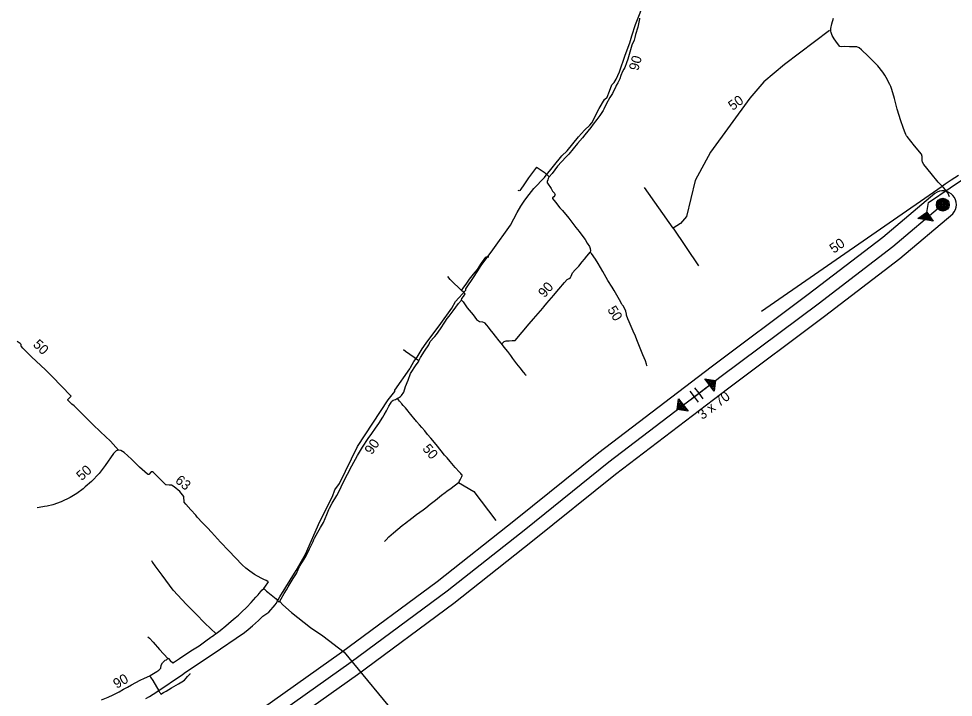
# Model space of a CAD drawing. Extents: x -444817 to -434929, y -1145681 to -1129851.
# Drawn here: x -442712 to -441954, y -1130962 to -1130412 of the extents above; entities that cross this region are included whole.
import ezdxf

# ---------------------------------------------------------------- set-up
doc = ezdxf.new("R2010")
doc.units = 0
for name, color, linetype in [('Vrstva 10', 7, 'Continuous'), ('Vrstva 11', 7, 'Continuous'), ('Vrstva 13', 7, 'Continuous'), ('Vrstva 15', 7, 'Continuous'), ('Vrstva 18', 7, 'Continuous'), ('Vrstva 27', 7, 'Continuous'), ('Vrstva 30', 7, 'Continuous'), ('Vrstva 35', 7, 'Continuous'), ('Vrstva 38', 7, 'Continuous'), ('Vrstva 58', 7, 'Continuous')]:
    doc.layers.add(name, color=color, linetype=linetype)

msp = doc.modelspace()

# ---------------------------------------------------------------- linework, layer by layer
at = {"layer": 'Vrstva 10'}
for p, q in [((-442167.4, -1130713.98), (-442164.01, -1130718.43)), ((-442163.61, -1130711.1), (-442160.22, -1130715.55)), ((-442160.22, -1130715.55), (-442156.83, -1130720.01)), ((-442164.01, -1130718.43), (-442160.62, -1130722.89))]:
    msp.add_line(p, q, dxfattribs=at)
for points in [[(-442543.87, -1131005.45), (-442442.17, -1130933.34), (-442364.32, -1130875.82), (-442300.6, -1130825.49), (-442233.21, -1130771.17), (-442142.12, -1130701.84), (-442063.4, -1130643.16), (-442002.57, -1130596.62), (-441962.3, -1130562.43)], [(-442172.7, -1130725.05), (-442162.12, -1130716.99), (-442151.53, -1130708.94)]]:
    msp.add_lwpolyline(points, dxfattribs=at)
for points in [[(-442155.35, -1130703.92), (-442146.52, -1130705.12), (-442147.72, -1130713.95)], [(-442153.77, -1130704.85), (-442147.31, -1130705.72), (-442148.18, -1130712.18)], [(-442152.19, -1130705.77), (-442148.09, -1130706.32), (-442148.65, -1130710.41)], [(-442150.61, -1130706.69), (-442148.88, -1130706.92), (-442149.12, -1130708.64)], [(-442176.52, -1130720.03), (-442168.88, -1130730.06), (-442177.71, -1130728.86)], [(-442176.05, -1130721.8), (-442170.46, -1130729.14), (-442176.93, -1130728.26)], [(-442175.58, -1130723.57), (-442172.05, -1130728.22), (-442176.14, -1130727.66)], [(-442175.12, -1130725.34), (-442173.63, -1130727.3), (-442175.35, -1130727.06)]]:
    msp.add_lwpolyline(points, close=True, dxfattribs=at)
at = {"layer": 'Vrstva 11'}
for radius in [5.25, 4.55, 3.85, 3.15, 2.45, 1.75, 1.05, 0.35]:
    msp.add_circle((-441962.15, -1130562.69), radius, dxfattribs=at)
at = {"layer": 'Vrstva 15'}
for points in [[(-441968.62, -1130553.5), (-442010.81, -1130589.32), (-442071.36, -1130635.64), (-442150.07, -1130694.32), (-442241.33, -1130763.77), (-442308.79, -1130818.15), (-442372.32, -1130868.34), (-442449.95, -1130925.69), (-442551.7, -1130997.84)], [(-442511.53, -1130996.32), (-442437.05, -1130943.51), (-442358.97, -1130885.82), (-442295.07, -1130835.35), (-442227.76, -1130781.09), (-442136.83, -1130711.89), (-442058.1, -1130653.2), (-441997, -1130606.45), (-441954.08, -1130570.1)]]:
    msp.add_lwpolyline(points, dxfattribs=at)
msp.add_arc((-441962.27, -1130562.6), 11.1, 317.50257, 124.90759, dxfattribs=at)
at = {"layer": 'Vrstva 18'}
msp.add_lwpolyline([(-441975.84, -1130573.79), (-441973.68, -1130560.84), (-441938.52, -1130537.09), (-441896.26, -1130510.56), (-441885.41, -1130506.39), (-441864.4, -1130498), (-441823.77, -1130476.32), (-441821.75, -1130474.03), (-441814.82, -1130469.54), (-441767.01, -1130447.94), (-441721.98, -1130422.65), (-441673.35, -1130395.2), (-441719.61, -1130299.27), (-441714.03, -1130296.36)], dxfattribs=at)
for points in [[(-441969.98, -1130576.19), (-441982.36, -1130573.88), (-441975.01, -1130568.84)], [(-441971.51, -1130575.19), (-441980.57, -1130573.5), (-441975.2, -1130569.82)], [(-441973.04, -1130574.2), (-441978.78, -1130573.12), (-441975.38, -1130570.79)], [(-441974.58, -1130573.2), (-441976.99, -1130572.75), (-441975.56, -1130571.76)]]:
    msp.add_lwpolyline(points, close=True, dxfattribs=at)
at = {"layer": 'Vrstva 27'}
for points in [[(-442208.2, -1130411.49), (-442208.3, -1130411.94), (-442209.73, -1130418.71), (-442211.51, -1130424.6), (-442212.15, -1130427.18), (-442212.65, -1130429.19), (-442214.45, -1130433.28), (-442216.13, -1130439.14), (-442217.86, -1130444.64), (-442218.73, -1130447.74), (-442220.3, -1130451.38), (-442221.02, -1130452.76), (-442222.1, -1130454.69), (-442223.41, -1130457.92), (-442224.26, -1130460.77), (-442225.8, -1130463.81), (-442227.12, -1130465.98), (-442227.4, -1130466.84), (-442227.85, -1130467.76), (-442228.85, -1130469.66), (-442230.13, -1130472.5), (-442232.42, -1130475.81), (-442235.19, -1130481.27), (-442237.14, -1130485.18), (-442237.76, -1130486.34), (-442240.52, -1130490.32), (-442242.89, -1130493.56), (-442245.96, -1130497.55), (-442247.87, -1130500)], [(-441994.27, -1130500), (-441996.11, -1130494.73), (-441999.09, -1130485.29), (-442001.43, -1130476.55), (-442003.49, -1130469.28), (-442004.29, -1130466.9), (-442005.11, -1130465.27), (-442008.04, -1130459.62), (-442009.22, -1130457.82), (-442010.94, -1130455.32), (-442014.99, -1130450.03), (-442022.65, -1130442.38), (-442028.22, -1130437.2), (-442030.04, -1130435.62), (-442031.87, -1130434.82), (-442035.46, -1130434.73), (-442037.75, -1130434.6), (-442042.06, -1130434.37), (-442043.97, -1130434.71), (-442045.64, -1130434.34), (-442046.75, -1130433.21), (-442049.07, -1130430.15), (-442050.26, -1130428.27), (-442051.88, -1130425.52), (-442052.67, -1130423.1), (-442052.98, -1130422.13), (-442053.1, -1130419.95), (-442052.32, -1130416.01), (-442050.91, -1130411.56)], [(-442247.87, -1130500), (-442250.29, -1130503.1), (-442252.71, -1130506.19), (-442254.54, -1130508.41), (-442258.54, -1130513.22), (-442265.66, -1130521.68), (-442268.09, -1130524.15), (-442274.83, -1130531.51), (-442279.22, -1130537.52), (-442281.59, -1130540.08)], [(-441949.36, -1130538.97), (-441955.35, -1130542.79), (-441960.27, -1130546.03), (-441962.44, -1130547.59), (-441962.74, -1130547.8), (-441965.95, -1130544.37), (-441971.72, -1130537.34), (-441977.54, -1130530.04), (-441978.58, -1130528.29), (-441978.93, -1130526.93), (-441978.82, -1130523.52), (-441979.49, -1130521.79), (-441985.14, -1130514.87), (-441991.07, -1130507.53), (-441991.6, -1130506.77), (-441992.03, -1130505.89), (-441993.24, -1130502.96), (-441994.27, -1130500)], [(-442291.86, -1130532.26), (-442293.5, -1130534.34), (-442298.37, -1130540.81), (-442302.22, -1130546.52), (-442304.59, -1130550.11), (-442305.44, -1130551.26), (-442306.03, -1130551.54), (-442306.68, -1130551.07)], [(-442281.59, -1130540.08), (-442284.89, -1130537.26), (-442291.32, -1130532.73), (-442291.86, -1130532.26)], [(-442281.59, -1130540.08), (-442281.92, -1130540.44), (-442282.37, -1130541.45), (-442282.77, -1130542.51), (-442283.29, -1130543.91), (-442283.21, -1130545.01), (-442282.95, -1130545.37), (-442280.01, -1130549.48), (-442278.78, -1130551.68), (-442277.22, -1130553.46), (-442276.85, -1130554.39), (-442276.61, -1130554.7), (-442276.87, -1130555.21), (-442277.89, -1130556.25), (-442278.86, -1130557.03), (-442278.95, -1130557.34), (-442278.8, -1130557.7), (-442276.4, -1130560.61), (-442272.79, -1130565.13), (-442270.84, -1130567.52), (-442265.7, -1130573.69), (-442259.83, -1130581.08), (-442257.28, -1130584.49), (-442254.94, -1130587.37), (-442252.29, -1130591.04), (-442250.71, -1130593.82), (-442248.82, -1130596.69), (-442248.31, -1130598.28), (-442248.06, -1130600.2), (-442248.38, -1130601.16)], [(-441956.63, -1130556.34), (-441958.03, -1130553.11), (-441959.86, -1130550.64), (-441961.52, -1130548.79), (-441962.74, -1130547.8)], [(-442320.61, -1130675.22), (-442319.77, -1130675.24), (-442318, -1130673.6), (-442316.5, -1130673.1), (-442314.08, -1130673.02), (-442311.65, -1130672.81), (-442309.84, -1130672.87), (-442309.29, -1130672.67), (-442303.37, -1130665.98), (-442297.79, -1130659.41), (-442294.18, -1130655.11), (-442292.52, -1130653.2), (-442290.57, -1130651.03), (-442286.77, -1130646.54), (-442285.98, -1130645.6), (-442283.39, -1130642.49), (-442279.7, -1130638.26), (-442277.87, -1130636.14), (-442276.71, -1130634.79), (-442273.61, -1130631.14), (-442269.14, -1130625.83), (-442266.9, -1130623.42), (-442265.42, -1130622.43), (-442264.32, -1130621.65), (-442263.64, -1130620.72), (-442263.12, -1130619.28), (-442262.65, -1130617.96), (-442260.54, -1130615.63), (-442257.6, -1130612.52), (-442254.77, -1130609.08), (-442253.03, -1130606.84), (-442251.01, -1130604.47), (-442249.25, -1130602.43), (-442248.38, -1130601.16)], [(-442201.94, -1130693.46), (-442202.21, -1130693.17), (-442202.65, -1130691.93), (-442203.45, -1130689.31), (-442205.53, -1130684.39), (-442208.76, -1130676.37), (-442210.5, -1130672.15), (-442211.65, -1130669.38), (-442213.38, -1130665.19), (-442216.65, -1130657.73), (-442217.63, -1130655.34), (-442218.73, -1130652.39), (-442218.94, -1130651.34), (-442219.32, -1130649.02), (-442219.85, -1130647.62), (-442221.48, -1130644.78), (-442222.29, -1130643.91), (-442222.7, -1130643.48), (-442224.43, -1130639.7), (-442227.65, -1130634.29), (-442228.93, -1130632.16), (-442230.36, -1130629.68), (-442233.87, -1130624.07), (-442238.08, -1130616.86), (-442241.92, -1130610.41), (-442244.07, -1130606.83), (-442247.26, -1130602.3), (-442248.38, -1130601.16)], [(-442352.69, -1130632.19), (-442350.93, -1130629.68), (-442349.03, -1130627.11), (-442346.18, -1130623.08), (-442343.03, -1130619.16), (-442339.76, -1130615.19), (-442336.51, -1130610), (-442332.91, -1130605.29), (-442332.52, -1130605.05), (-442331.52, -1130604.93), (-442330.64, -1130604.95)], [(-442353.75, -1130631.17), (-442360.16, -1130624.99), (-442361.82, -1130623.33), (-442363.89, -1130620.79)], [(-442352.69, -1130632.19), (-442353.49, -1130631.42), (-442353.75, -1130631.17)], [(-442352.75, -1130640.01), (-442352.32, -1130638.86), (-442351.13, -1130637.01), (-442349.75, -1130635.02), (-442351.18, -1130633.69), (-442352.69, -1130632.19)], [(-442387.32, -1130689.35), (-442386.01, -1130686.48), (-442382.71, -1130681.51), (-442379.25, -1130676.28), (-442378.01, -1130673.54), (-442374.87, -1130670.06), (-442374.38, -1130669.55), (-442373.1, -1130667.99), (-442369.84, -1130663.28), (-442366.23, -1130657.88), (-442364.28, -1130654.99), (-442362.81, -1130653.05), (-442359.56, -1130648.67), (-442355.25, -1130642.91), (-442352.75, -1130640.01)], [(-442352.75, -1130640.01), (-442351.33, -1130641.47), (-442348.04, -1130646.25), (-442343.34, -1130651.95), (-442340.59, -1130655.7), (-442338.07, -1130657.38), (-442335.73, -1130657.72), (-442334.28, -1130658.1), (-442334.08, -1130658.35), (-442332.49, -1130660.29), (-442331.1, -1130661.99), (-442329.7, -1130663.86), (-442327.39, -1130666.83), (-442325.44, -1130669.32), (-442322.51, -1130673.1), (-442320.92, -1130675), (-442320.61, -1130675.22)], [(-442631.13, -1130761.67), (-442633.22, -1130759.18), (-442637.66, -1130754.31), (-442645.64, -1130746.8), (-442652, -1130740.82), (-442660.31, -1130732.56), (-442666.92, -1130725.88), (-442669.04, -1130724.31), (-442672.06, -1130721.31), (-442672.23, -1130721.05), (-442672.06, -1130720.75), (-442669.36, -1130717.93), (-442677.57, -1130709.44), (-442684.69, -1130702.29), (-442690.38, -1130696.7), (-442694.05, -1130693.1), (-442701.54, -1130685.97), (-442708.79, -1130678.92), (-442709.62, -1130677.75), (-442709.92, -1130677.36), (-442710.08, -1130675.98), (-442710.88, -1130675.26), (-442713.18, -1130673.54)], [(-442320.61, -1130675.22), (-442318.48, -1130678.11), (-442315.37, -1130681.85), (-442313, -1130684.89), (-442311.23, -1130687.28), (-442307.97, -1130691.59), (-442305.32, -1130695.09), (-442302.73, -1130698.36), (-442300.88, -1130700.73), (-442300.45, -1130701.22)], [(-442387.32, -1130689.35), (-442391.21, -1130686.5), (-442398.2, -1130681.76), (-442399.9, -1130680.39)], [(-442404.65, -1130719.63), (-442403.79, -1130719.17), (-442402.14, -1130718.14), (-442401.31, -1130717.43), (-442399.57, -1130714.59), (-442398.21, -1130710.1), (-442396.1, -1130704.97), (-442393.96, -1130699.64), (-442389.62, -1130692.47), (-442387.62, -1130690), (-442387.32, -1130689.35)], [(-442500, -1130884.03), (-442498.94, -1130882.24), (-442496.5, -1130877.86), (-442494.71, -1130874.85), (-442493.35, -1130872.5), (-442490.9, -1130868.51), (-442489.18, -1130865.74), (-442486.72, -1130861.6), (-442485.2, -1130858.46), (-442484.18, -1130856.15), (-442481.71, -1130852.34), (-442478.99, -1130847.84), (-442476, -1130841.74), (-442473.1, -1130835.79), (-442472.63, -1130834.21), (-442472.03, -1130833.09), (-442469.21, -1130828.13), (-442467.07, -1130824.33), (-442464.75, -1130820.34), (-442463.33, -1130817.18), (-442462.07, -1130813.91), (-442460.31, -1130809.81), (-442459.82, -1130808.79), (-442457.54, -1130804.64), (-442453.9, -1130798.59), (-442452.25, -1130795.41), (-442450.47, -1130791.56), (-442448.47, -1130787.49), (-442445.3, -1130781.06), (-442441.74, -1130774.54), (-442437.18, -1130766.17), (-442433.17, -1130759.16), (-442428.46, -1130752.2), (-442425.55, -1130748.19), (-442422.5, -1130743.9), (-442419.83, -1130740.21), (-442416.57, -1130734.92), (-442415.44, -1130733.09), (-442413.68, -1130729.78), (-442411.64, -1130725.93), (-442410.44, -1130723.75), (-442409.89, -1130723.02), (-442409.41, -1130722.21), (-442408.03, -1130721.23), (-442406.28, -1130720.57), (-442404.65, -1130719.63)], [(-442404.31, -1130825.74), (-442400.75, -1130822.87), (-442397.82, -1130820.7), (-442396.27, -1130819.36), (-442395.56, -1130818.81), (-442393.06, -1130816.86), (-442389.17, -1130814), (-442383.92, -1130810.07), (-442381.75, -1130808.44), (-442378.08, -1130805.45), (-442373.92, -1130802.27), (-442368.88, -1130798.25), (-442366.08, -1130796.12), (-442364.62, -1130795.05), (-442361.02, -1130792.4), (-442355.27, -1130788), (-442354.61, -1130787.25), (-442354.21, -1130786.56), (-442353.84, -1130785.73), (-442352.52, -1130783.05), (-442352.21, -1130782.23), (-442352.21, -1130782.2), (-442352.24, -1130781.82), (-442352.58, -1130781.38), (-442353.17, -1130780.71), (-442354.3, -1130779.43), (-442357.73, -1130775.74), (-442361.93, -1130770.89), (-442364.33, -1130767.96), (-442366.37, -1130765.64), (-442369.22, -1130762.35), (-442373.4, -1130757.23), (-442377.55, -1130752.09), (-442380.25, -1130749.07), (-442382.55, -1130746.15), (-442385.01, -1130743.32), (-442386.82, -1130741.29), (-442389.11, -1130738.47), (-442389.68, -1130737.77), (-442390.26, -1130737.08), (-442393.73, -1130732.9), (-442395.13, -1130731.1), (-442395.89, -1130730.17), (-442398.27, -1130727.48), (-442400.03, -1130725.42), (-442401.01, -1130724.28), (-442401.65, -1130723.48), (-442401.97, -1130723.13), (-442402.91, -1130722.08), (-442404.6, -1130719.69), (-442404.65, -1130719.63)], [(-442631.13, -1130761.67), (-442631.29, -1130761.72), (-442633.01, -1130762.3), (-442634.97, -1130764.35), (-442641.8, -1130774.19), (-442646.64, -1130780.62), (-442653.07, -1130787.17), (-442657.97, -1130791.51), (-442659.65, -1130793), (-442664.92, -1130796.9), (-442670.3, -1130800.21), (-442677.67, -1130803.68), (-442684.33, -1130806.12), (-442688.95, -1130807.11), (-442691.11, -1130807.51), (-442695.3, -1130808.24), (-442697.13, -1130808.46)], [(-442602.71, -1130779.69), (-442603.48, -1130779.37), (-442604.45, -1130779.32), (-442606.52, -1130781.39), (-442606.86, -1130781.47), (-442607.46, -1130781.28), (-442613.91, -1130775.41), (-442620.53, -1130768.88), (-442626.35, -1130763.61), (-442629.05, -1130762.08), (-442630.9, -1130761.59), (-442631.13, -1130761.67)], [(-442592.28, -1130789.81), (-442592.7, -1130789.71), (-442592.71, -1130789.72), (-442602.71, -1130779.69)], [(-442577.85, -1130803.83), (-442578.01, -1130799.34), (-442581.21, -1130795.23), (-442585.74, -1130791.57), (-442587.9, -1130790.01), (-442589.92, -1130789.96), (-442592.28, -1130789.81)], [(-442567.09, -1130815.96), (-442568.42, -1130814.49), (-442572.38, -1130809.95), (-442576.42, -1130805.44), (-442576.32, -1130805.54), (-442577.85, -1130803.83)], [(-442513.19, -1130873.94), (-442511.81, -1130871.97), (-442509.75, -1130869.31), (-442509.34, -1130868.5), (-442509.73, -1130868.07), (-442511.08, -1130867.46), (-442513.19, -1130866.56), (-442515.32, -1130865.48), (-442520.57, -1130862.51), (-442524.45, -1130859.74), (-442526.55, -1130858.15), (-442527.59, -1130857.37), (-442530.6, -1130854.55), (-442536.15, -1130848.89), (-442541.4, -1130843.45), (-442548.16, -1130836.24), (-442555.55, -1130828.17), (-442558.88, -1130824.72), (-442562.93, -1130820.52), (-442567.09, -1130815.96)], [(-442415.28, -1130835.64), (-442413.95, -1130834.39), (-442411.65, -1130832.01), (-442407.94, -1130828.86), (-442404.31, -1130825.74)], [(-442551.99, -1130910.44), (-442556.22, -1130906.67), (-442561.34, -1130901.65), (-442568.01, -1130894.68), (-442575.79, -1130886.87), (-442586.71, -1130875.16), (-442595.64, -1130862.98), (-442601.36, -1130855.51), (-442603.29, -1130852.73), (-442603.65, -1130852.12), (-442603.92, -1130851.48)], [(-442551.99, -1130910.44), (-442551.72, -1130910.23), (-442548.56, -1130907.88), (-442543.89, -1130904.2), (-442539.48, -1130900.44), (-442536.29, -1130897.59), (-442533.59, -1130895.42), (-442531.1, -1130893.04), (-442527.03, -1130889), (-442523.49, -1130885.17), (-442519.55, -1130880.9), (-442517.68, -1130878.91), (-442516.78, -1130877.96), (-442515.51, -1130876.3), (-442514.6, -1130875.11), (-442513.19, -1130873.94)], [(-442513.19, -1130873.94), (-442511.02, -1130875.96), (-442509.81, -1130876.82), (-442503.12, -1130882.28), (-442502.01, -1130883.66), (-442500.69, -1130885.02), (-442500.2, -1130884.37), (-442500, -1130884.03)], [(-442607.15, -1130912.96), (-442605.99, -1130914.13), (-442602.79, -1130917.45), (-442597.68, -1130923.38), (-442591.13, -1130930.6)], [(-442591.13, -1130930.6), (-442590.74, -1130930.25), (-442589.08, -1130932.18), (-442587.04, -1130934.19), (-442585.49, -1130933.21), (-442581.56, -1130930.63), (-442577.28, -1130927.7), (-442571.11, -1130923.6), (-442565.71, -1130920.22), (-442560.1, -1130916.22), (-442555.98, -1130913.22), (-442555.34, -1130912.68), (-442553.86, -1130911.86), (-442551.99, -1130910.44)], [(-442605.65, -1130944.6), (-442605.32, -1130944.44), (-442602.56, -1130942.85), (-442600.05, -1130941.28), (-442598.34, -1130940.09), (-442597.51, -1130939.2), (-442596.67, -1130938.47), (-442596.32, -1130935.94), (-442595.34, -1130934.22), (-442594.72, -1130933.45), (-442593.07, -1130932.02), (-442592.19, -1130931.63), (-442591.32, -1130930.77), (-442591.13, -1130930.6)], [(-442596.62, -1130959.52), (-442594.54, -1130958.31), (-442592.25, -1130956.98), (-442587.94, -1130954.38), (-442582.46, -1130951.02), (-442579.71, -1130949.63), (-442577.61, -1130948.1), (-442576.05, -1130946.54), (-442574.94, -1130945.32), (-442573.08, -1130943.41), (-442572.79, -1130943.11), (-442572.81, -1130942.94), (-442572.84, -1130942.78)], [(-442644.93, -1130964.24), (-442639.49, -1130962.01), (-442635.36, -1130959.97), (-442630.59, -1130957.63), (-442626.89, -1130955.51), (-442623.7, -1130953.84), (-442620.43, -1130951.84), (-442613.54, -1130948.05), (-442609.85, -1130946.56), (-442605.65, -1130944.6)], [(-442605.65, -1130944.6), (-442605.08, -1130945.88), (-442603.3, -1130948.34), (-442598.28, -1130956.7), (-442597.66, -1130957.79), (-442597.39, -1130958.09), (-442597.15, -1130958.56), (-442596.62, -1130959.52)]]:
    msp.add_lwpolyline(points, dxfattribs=at)
at = {"layer": 'Vrstva 35'}
for p, q in [((-442109.22, -1130649.14), (-441962.74, -1130547.8)), ((-442180.87, -1130581.64), (-442160.31, -1130612.19))]:
    msp.add_line(p, q, dxfattribs=at)
for points in [[(-442054.2, -1130421.58), (-442090.58, -1130449.08), (-442107.45, -1130463.21), (-442118.7, -1130476.23), (-442150.67, -1130520.05), (-442163.17, -1130542.96), (-442170.21, -1130572.16), (-442174.95, -1130578.08), (-442180.87, -1130581.64), (-442204.28, -1130548.79)], [(-442355.27, -1130788), (-442342.74, -1130795.22), (-442324.77, -1130818.79)], [(-442500.2, -1130884.37), (-442497.82, -1130887.18), (-442490.69, -1130893.39), (-442475.17, -1130905.39), (-442465.35, -1130912.21), (-442448.01, -1130925.49), (-442401.17, -1130982.2), (-442388.78, -1130994.41), (-442378.11, -1131004.41), (-442338.15, -1131041.79), (-442319.45, -1131059.9), (-442262, -1131115.01)]]:
    msp.add_lwpolyline(points, dxfattribs=at)
at = {"layer": 'Vrstva 58'}
for points in [[(-442509.18, -1130893.03), (-442503.86, -1130887.08), (-442503.05, -1130886.01), (-442500.19, -1130880.75), (-442486.96, -1130859.4), (-442479.34, -1130846.03), (-442467.57, -1130819.67), (-442464.96, -1130814.41), (-442463.13, -1130810.27), (-442457.32, -1130799.28), (-442455.43, -1130793.9), (-442451.66, -1130788.8), (-442437.16, -1130758.81), (-442412.14, -1130720.81), (-442406.68, -1130714.08), (-442406.78, -1130713), (-442394.69, -1130695.86), (-442394.05, -1130694.78), (-442391.45, -1130689.81), (-442388.76, -1130686.34), (-442384.63, -1130679.66), (-442381.3, -1130674.88), (-442369.35, -1130659.06), (-442360.63, -1130646.64), (-442357.61, -1130641.17), (-442349.25, -1130632.1), (-442349.22, -1130630.83), (-442342.3, -1130620.88), (-442339.87, -1130617.14), (-442336.8, -1130612.09), (-442327.15, -1130599.28), (-442312.93, -1130579.28), (-442310.16, -1130574.11), (-442307.48, -1130569.01), (-442304.49, -1130563.8), (-442301.33, -1130559.11), (-442297.77, -1130554.45), (-442294.1, -1130549.55), (-442285.45, -1130540.58), (-442284.89, -1130539.87), (-442271.3, -1130523), (-442266.92, -1130519.08), (-442257.88, -1130507.58), (-442252.78, -1130502.25), (-442248.6, -1130498.27), (-442247.06, -1130496.33), (-442241.03, -1130484.83), (-442236.73, -1130477.37), (-442234.42, -1130475.63), (-442232.55, -1130470.65), (-442230.72, -1130465.43), (-442228.78, -1130463.7), (-442227.15, -1130460.84), (-442224.46, -1130455.07), (-442219.98, -1130441.43), (-442216.03, -1130431.4), (-442214.43, -1130425.83), (-442211.44, -1130416.63), (-442203.63, -1130396.6)], [(-442608.75, -1130963.13), (-442605.79, -1130961.53), (-442602.87, -1130959.46), (-442599.81, -1130957.52), (-442579, -1130943.47), (-442576.59, -1130941.76), (-442555.02, -1130927.44), (-442528.93, -1130909.45), (-442525.77, -1130907.12), (-442522.2, -1130904.12), (-442517.4, -1130899.83), (-442514.02, -1130896.31), (-442509.18, -1130893.03)]]:
    msp.add_lwpolyline(points, dxfattribs=at)

# ---------------------------------------------------------------- texts
at = {"layer": 'Vrstva 13'}
msp.add_text('3 x 70', height=8, rotation=37.27331, dxfattribs=at).set_placement((-442157.22, -1130737.32))
at = {"layer": 'Vrstva 30'}
for s, rotation, p in [('90', 74.32348, (-442209.41, -1130454.63)), ('90', 49.00577, (-442285.35, -1130638.63)), ('50', 302.03292, (-442234.66, -1130647.78)), ('50', 315.80129, (-442700.97, -1130676.73)), ('90', 55.91284, (-442425.43, -1130765.93)), ('50', 310.31289, (-442384.85, -1130760.8)), ('50', 41.53177, (-442660.96, -1130786.91)), ('63', 321.05597, (-442585.64, -1130787.34)), ('90', 29.81154, (-442632.53, -1130955.3))]:
    msp.add_text(s, height=8, rotation=rotation, dxfattribs=at).set_placement(p)
at = {"layer": 'Vrstva 38'}
for rotation, p in [(35.83178, (-442132.67, -1130486.73)), (34.67656, (-442050.62, -1130602.52))]:
    msp.add_text('50', height=8, rotation=rotation, dxfattribs=at).set_placement(p)

doc.saveas('drawing.dxf')
